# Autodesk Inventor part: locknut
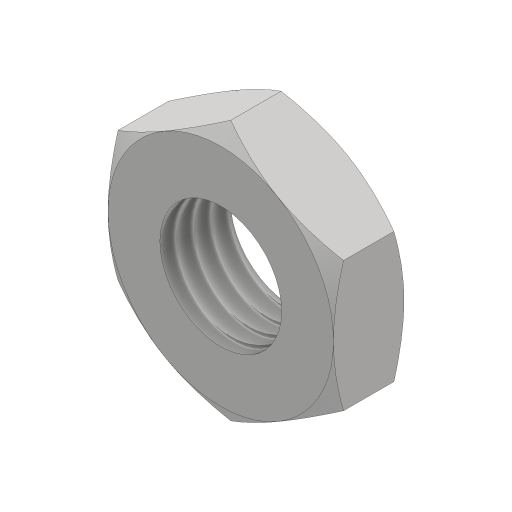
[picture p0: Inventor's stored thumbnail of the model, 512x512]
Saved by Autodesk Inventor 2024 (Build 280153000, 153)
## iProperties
Created: 2016-05
Part Number: locknut
Material: Generic
Document SubType Name: Modeling
Designer: CADCIM
Density: 1 g/cm^3
Appearance: Default
Author: CADCIM
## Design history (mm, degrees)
sketch "Sketch1"
  geometry: L1 (9.6, -5.543)-(0, -11.085); L2 (0, -11.085)-(-9.6, -5.543); L3 (-9.6, -5.543)-(-9.6, 5.543); L4 (-9.6, 5.543)-(0, 11.085); L5 (0, 11.085)-(9.6, 5.543); L6 (9.6, 5.543)-(9.6, -5.543); 2 further points
  constraints: 12 end point, 1 coincident, 1 vertical alignment, 13 other
  dimensions: "d0" = 19.2 distance between parallel lines of L3 L6
extrude "Extrusion1" new body sketch "Sketch1" distance "d1" = 6; taper "d2" = 0 deg
sketch "Sketch2"
  geometry: L1 (0, 11.085)-(-9.6, 5.543) reference; C1 r 9.6 at (0, 0); 1 further point
  constraints: 1 centre point, 1 coincident, 1 tangent
extrude "Extrusion2" sketch "Sketch2" distance "d3" = 10.8; taper "d4" = 60 deg
workplane "Work Plane1"
sketch "Sketch3"
  geometry: L1 (0, -11.085)-(9.6, -5.543) reference; C1 r 9.6 at (0, 0); 1 further point
  constraints: 1 centre point, 1 coincident, 1 tangent
extrude "Extrusion3" sketch "Sketch3" distance "d5" = 10.8; taper "d6" = 60 deg
hole "Hole1" diameter "d9" = 10.376; stored, may be unused: countersink angle "d13" = 90 deg, drill point angle "d15" = 118 deg; dims "d7" = 10, "d8" = 10, "d10" = 24, "d11" = 4, "d12" = 2, "d14" = 31.3
body "Solid1"
sketch "Sketch4"
  geometry: 1 further point
